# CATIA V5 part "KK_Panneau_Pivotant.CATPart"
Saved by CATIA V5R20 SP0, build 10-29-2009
Part number: Panneau pivotant
Bounding box of the stored display mesh (mm): x -336.888 to 178.601, y -288 to 1376, z -1407.979 to 175.883
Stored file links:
  G:\Khaled_CFAO_2011\ST2M\ST2M_GR2\aboulegue\Khaled\CAD_thinkMOTION\KK_Panneau_Pivotant.CATPart
  G:\Khaled_CFAO_2011\ST2M\ST2M_GR2\aboulegue\Khaled\CAD_thinkMOTION\KK_Train_Atterrissage.CATProduct
  G:\Khaled_CFAO_2011\ST2M\ST2M_GR2\aboulegue\Khaled\CAD_thinkMOTION\KK_SquelettePanneau_Pivotant.CATPart
  G:\Khaled_CFAO_2011\ST2M\ST2M_GR2\aboulegue\Khaled\CAD_thinkMOTION\KK_SqueletteGeneral.CATPart
  G:\Khaled_CFAO_2011\ST2M\ST2M_GR2\aboulegue\Khaled\CAD_thinkMOTION\KK_SqueletteVerin.CATPart
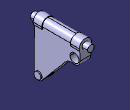
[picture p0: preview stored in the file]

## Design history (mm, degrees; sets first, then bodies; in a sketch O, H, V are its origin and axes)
External parameters (linked from other documents)
  `External.Longueur panneau pivotant` = 1056 mm
Set1
  Plane1 "Plan reference": linked copy from another document
  Point1: linked copy from another document
  Point2: linked copy from another document
  Line1: linked copy from another document
  Line2: linked copy from another document
  Plane2 "Plan reference 2": linked copy from another document
  Point3: linked copy from another document
  Line3: linked copy from another document
  Plane3 "Plan panneau pivotant": linked copy from another document
  Point4 "Point.10": linked copy from another document
  Line4: linked copy from another document
  Point5: linked copy from another document
Body1 (main body)
  Sketch1 on Plane2, origin (0, 0, 0), H (-1, 0, 0), V (0, 0, 1)
    point P1 (0, 160)
    point P2 (0, -1408)
    line L1 (0, -1408) -> (-144, -1408)
    point P3 (-144, -1408)
    line L2 (-144, -1408) -> (-159.9897, -1.8192)
    point P4 (-159.9897, -1.8192)
    arc A1 centre (0, 0) radius 160 from (-159.9897, -1.8192) to (0, 160) cw
    reference projected point E1 (0, 0) from Point3
    reference projected line E2 (200, -1280) -> (-200, -1280) from Line3
    reference projected line E3 (0, 0) -> (0, -1280) from Line2
    point P6 (0, 160)
    point P7 (159.9897, -1.8192)
    arc A2 centre (0, 0) radius 160 from (159.9897, -1.8192) to (0, 160) ccw
    point P9 (144, -1408)
    line L3 (144, -1408) -> (159.9897, -1.8192)
    point P10 (0, -1408)
    line L4 (0, -1408) -> (144, -1408)
    length L1 = 144
    radius A1 = 160
    distance L1 E2 = 128
    angle L2 E3 = 179.3485
    horizontal: L1 H
    tangency: A1 L2
    concentricity: A1 E1
    symmetry: P1 P6 V, P4 P7 V, A1 A2 V, P3 P9 V, L2 L3 V, P2 P10 V, L1 L4 V
    coincidence: P1 P6
  Sketch2 on Plane1, origin (0, 0, 0), H (0, 1, 0), V (0, 0, 1)
    line L1 (-96, 160) -> (1216, 160)
    line L2 (1216, 160) -> (1216, -320)
    arc A1 centre (1056, -320) radius 160 from (1216, -320) to (1019.4894, -475.7786) cw
    arc A2 centre (966, -704) radius 234.4059 from (1019.4894, -475.7786) to (787.48, -552.0898) ccw
    point P6 (966, -704)
    line L3 (787.48, -552.0898) -> (97.4829, -1362.9523)
    arc A3 centre (0, -1280) radius 128 from (97.4829, -1362.9523) to (-127.9683, -1277.1534) cw
    line L4 (-127.9683, -1277.1534) -> (-96, 160)
    reference projected point E1 (1056, -320) from Point1
    reference projected point E2 (0, -1280) from Point2
    reference projected line E3 (1056, 0) -> (0, 0) from Line1
    radius A3 = 128
    radius A1 = 160
    distance E3 L1 = 160
    length L1 = 1312 {= `External.Longueur panneau pivotant` +256mm}
    distance L2 P6 = 250
    distance P6 L1 = 864
    horizontal: L1 H
    vertical: L2 V
    tangency: A1 L2, A2 A1, A3 L3, L3 A2, A3 L4
    concentricity: E1 A1, A3 E2
  SolidCombine1: FirstComponentProfile Sketch1, FirstComponentDirection Sketch1, SecondComponentProfile Sketch2, SecondComponentDirection Sketch2
  Sketch3 on face of SolidCombine1 from Sketch2.L4, origin (0, -99.513, 2.0698), H (1, 0, 0), V (0, 0.0222, 0.9998)
    line L1 (-64, -1429.5397) -> (-64, -1205.5397)
    arc A1 centre (0, -1205.5397) radius 64 from (-64, -1205.5397) to (64, -1205.5397) cw
    line L2 (64, -1205.5397) -> (64, -1429.5397)
    line L3 (64, -1429.5397) -> (-64, -1429.5397)
    reference projected line E1 (0, 0) -> (0, -1279.7233) from Line2
    reference projected line E2 (-200, -1279.5397) -> (200, -1279.5397) from Line3
    radius A1 = 64
    distance L2 E1 = 64
    distance L3 E2 = 150
    length L2 = 224
    vertical: L1 V
    tangency: A1 L1, L2 A1
    horizontal: L3 H
  Pocket1: profile Sketch3, direction (0, 0.9998, -0.0222), through (limit type 3)
  Sketch4 on Plane1, origin (0, 0, 0), H (0, 1, 0), V (0, 0, 1)
    circle A1 centre (1056, -320) radius 128
    point P1 (1056, -320)
    reference projected point E1 (1056, -320) from Point1
    radius A1 = 128
    coincidence: P1 E1
  Pocket2: profile Sketch4, direction (-1, 0, 0), length 200, mirrored extent
  Sketch5 on Plane1, origin (0, 0, 0), H (0, 1, 0), V (0, 0, 1)
    circle A1 centre (0, -1280) radius 80
    point P1 (0, -1280)
    reference projected point E1 (0, -1280) from Point2
    radius A1 = 80
    coincidence: E1 P1
  Pocket3: profile Sketch5, direction (-1, 0, 0), length 128, opposite side through (limit type 3)
  Sketch6 on Plane3, origin (0, 0, 0), H (1, 0, 0), V (0, 0, 1)
    line L1 (-337, -1240) -> (-135.9097, -1240)
    line L2 (-135.9097, -1240) -> (-135, -1320)
    line L3 (-135, -1320) -> (-337, -1320)
    line L4 (-337, -1320) -> (-337, -1240)
    reference projected line E1 (-159.9897, -1.8192) -> (-145.2241, -1300.3505) from edge [face of SolidCombine1 from Sketch1.L3 | face of SolidCombine1 from Sketch2.L4]
    reference projected line E2 (-144, -1408) -> (-145.2241, -1300.3505) from edge [face of SolidCombine1 from Sketch2.A3 | face of SolidCombine1 from Sketch1.L3]
    reference projected line E3 (0, -1280) -> (-256, -1280) from Line4
    distance L2 E2 = 10
    distance L1 E3 = 40
    length L4 = 80
    length L3 = 202
    horizontal: L1 H, L3 H
    vertical: L4 V
    parallelism: E1 L2
  Pad1: profile Sketch6, direction (0, -1, 0), length 24, mirrored extent
  Fillet1: radius 40, on edge [face of Pad1 from Sketch6.L4 | face of Pad1 from Sketch6.L1]; edge [face of Pad1 from Sketch6.L3 | face of Pad1 from Sketch6.L4]
  Fillet2: radius 24, on end face of Pad1; start face of Pad1
  Sketch7 on end face of Pad1, origin (0, -24, 0), H (1, 0, 0), V (0, 0, 1)
    circle A1 centre (-256, -1280) radius 24
    point P1 (-256, -1280)
    reference projected point E1 (-256, -1280) from Point4
    radius A1 = 24
    coincidence: E1 P1
  Pocket4: profile Sketch7, direction (0, 1, 0), through (limit type 6)
  Sketch8 on Plane2, origin (0, 0, 0), H (-1, 0, 0), V (0, 0, 1)
    circle A1 centre (0, 0) radius 176
    point P1 (0, 0)
    reference projected point E1 (0, 0) from Point3
    radius A1 = 176
    coincidence: P1 E1
  Pad2: profile Sketch8, direction (0, 1, 0), length 128, mirrored extent
  Sketch9 on face of SolidCombine1 from Sketch2.L2, origin (0, 1216, 0), H (-1, 0, 0), V (0, 0, 1)
    circle A1 centre (0, 0) radius 176
    point P1 (0, 0)
    reference projected point E1 (0, 0) from Point5
    radius A1 = 176
    coincidence: E1 P1
  Pad3: profile Sketch9, direction (0, -1, 0), length 256
  Sketch10 on start face of Pad2, origin (0, -128, 0), H (1, 0, 0), V (0, 0, 1)
    circle A1 centre (0, 0) radius 96
    point P1 (0, 0)
    reference projected point E1 (0, 0) from Point3
    radius A1 = 96
    coincidence: P1 E1
  Pad4: profile Sketch10, direction (0, -1, 0), length 160
  Sketch11 on face of Pad3, origin (0, 1216, 0), H (-1, 0, 0), V (0, 0, 1)
    circle A1 centre (0, 0) radius 96
    point P1 (0, 0)
    reference projected point E1 (0, 0) from Point5
    radius A1 = 96
    coincidence: E1 P1
  Pad5: profile Sketch11, direction (0, 1, 0), length 160
  Sketch12 on end face of Pocket3, origin (-128, 0, 0), H (0, 1, 0), V (0, 0, 1)
    circle A1 centre (0, -1280) radius 80
    reference projected circle E1 centre (0, -1280) radius 80 from edge [end face of Pocket3 | face of Pocket3 from Sketch5.A1]
    coincidence: E1 A1
  Pad6: profile Sketch12, direction (1, 0, 0), length 274
  Sketch13 on face of SolidCombine1 from Sketch1.L2, origin (159.9897, 0, -1.8192), H (0, 1, 0), V (0.0114, 0, 0.9999)
    circle A1 centre (0, -1278.2634) radius 101
    point P2 (0, -1177.2634)
    reference projected curve E1 from edge [face of SolidCombine1 from Sketch1.L2 | face of SolidCombine1 from Sketch2.A3]
    radius A1 = 101
    coincidence: A1 P2, P2 V
    concentricity: E1 A1
  Pad7: profile Sketch13, direction (0.9999, 0, -0.0114), length 32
